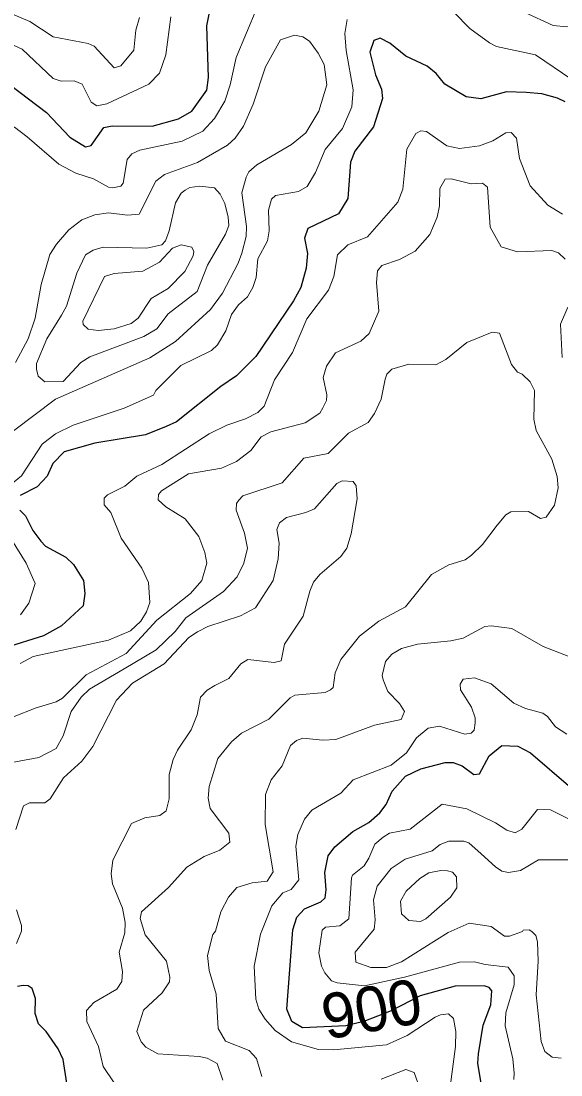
# Model space of a CAD drawing. Extents: x 294.2 to 320.3, y 7482.7 to 7510.7.
# Drawn here: x 318.172 to 319.135, y 7495.18 to 7497.059 of the extents above; entities that cross this region are included whole.
import ezdxf
from ezdxf.enums import TextEntityAlignment as Align

# ---------------------------------------------------------------- set-up
doc = ezdxf.new("R2010")
doc.units = 0
doc.header["$LTSCALE"] = 0.032
doc.layers.add('1', color=7, linetype='Continuous', lineweight=25)
doc.layers.add('2', color=7, linetype='Continuous', lineweight=13)
doc.layers.add('61', color=7, linetype='Continuous')

msp = doc.modelspace()

# ---------------------------------------------------------------- linework, layer by layer
at = {"layer": '1'}
for points in [[(318.1531, 7496.9451), (318.2173, 7496.896), (318.259, 7496.8522), (318.2869, 7496.8348), (318.2967, 7496.8371), (318.3194, 7496.8696), (318.3345, 7496.8726), (318.4059, 7496.8718), (318.4528, 7496.8847), (318.4766, 7496.8983), (318.5031, 7496.9361), (318.5061, 7496.9587), (318.5035, 7497.0509), (318.5126, 7497.0992)], [(319.1429, 7496.9152), (319.1293, 7496.922), (319.1013, 7496.9295), (319.0734, 7496.9318), (319.0382, 7496.9333), (318.9922, 7496.9205), (318.9665, 7496.9243), (318.9279, 7496.9469), (318.9124, 7496.9658), (318.8965, 7496.9786), (318.8588, 7496.9967), (318.83, 7497.0201), (318.8127, 7497.0285), (318.8013, 7497.0247), (318.7945, 7497.0035), (318.8043, 7496.9635), (318.8152, 7496.9378), (318.8167, 7496.9212), (318.8008, 7496.8706)], [(318.8008, 7496.8706), (318.7676, 7496.8275), (318.7596, 7496.8079), (318.7551, 7496.743), (318.7384, 7496.7158), (318.6833, 7496.6894), (318.6779, 7496.672)], [(318.6779, 7496.672), (318.6831, 7496.6448), (318.6809, 7496.6184), (318.671, 7496.5844), (318.6581, 7496.5602), (318.5908, 7496.4612), (318.5564, 7496.4265), (318.5285, 7496.4076), (318.4491, 7496.3449), (318.4309, 7496.3366), (318.3939, 7496.3215), (318.3031, 7496.3064), (318.2487, 7496.2913), (318.2283, 7496.2702), (318.2185, 7496.2475), (318.2004, 7496.2286), (318.1702, 7496.2135)], [(318.1693, 7496.1871), (318.1799, 7496.1773), (318.1927, 7496.1509), (318.2069, 7496.1318), (318.2152, 7496.1227), (318.2514, 7496.1031), (318.2656, 7496.0903), (318.2831, 7496.062), (318.2854, 7496.0386), (318.2823, 7496.0167), (318.2437, 7495.9812), (318.212, 7495.963), (318.1436, 7495.9419)], [(318.8843, 7495.3211), (318.8321, 7495.2947), (318.7834, 7495.2754), (318.7517, 7495.2679), (318.6739, 7495.2641), (318.655, 7495.2754), (318.6459, 7495.2973), (318.657, 7495.4387), (318.6638, 7495.4614), (318.6774, 7495.4765), (318.7067, 7495.4887), (318.7144, 7495.4957), (318.7163, 7495.5104), (318.7137, 7495.5411), (318.7201, 7495.5711), (318.7316, 7495.587), (318.7642, 7495.6144), (318.7923, 7495.6304), (318.812, 7495.6476), (318.8235, 7495.6624), (318.8344, 7495.6859), (318.858, 7495.7128), (318.8855, 7495.7262), (318.9289, 7495.737), (318.943, 7495.737), (318.9589, 7495.7313), (318.9799, 7495.716), (318.9902, 7495.7173), (319.0074, 7495.7492), (319.0298, 7495.7677), (319.0585, 7495.7664), (319.0808, 7495.7543), (319.1529, 7495.6925)], [(318.2533, 7495.1656), (318.2466, 7495.2075), (318.2378, 7495.2269), (318.2167, 7495.2576), (318.2029, 7495.271), (318.1968, 7495.2898), (318.1976, 7495.3165), (318.1918, 7495.3345), (318.1841, 7495.3389), (318.1752, 7495.3394), (318.1652, 7495.3378)], [(318.9966, 7495.2691), (319.01, 7495.3054), (319.0119, 7495.3303), (319.0074, 7495.3361), (318.9985, 7495.3393), (318.9468, 7495.3386), (318.8843, 7495.3211)], [(318.994, 7495.158), (318.987, 7495.2014), (318.9882, 7495.218), (318.9966, 7495.2691)]]:
    msp.add_lwpolyline(points, dxfattribs=at)
at = {"layer": '2'}
for points in [[(319.2034, 7496.931), (319.1945, 7496.9444), (319.1549, 7496.9553), (319.0898, 7496.9993), (319.0202, 7497.014), (319.0081, 7497.0204), (318.9729, 7497.0459), (318.9161, 7497.104)], [(319.1849, 7497.0893), (319.1632, 7497.0536), (319.146, 7497.0491), (319.1217, 7497.0516), (319.07, 7497.0753)], [(317.9833, 7496.8333), (317.9941, 7496.8537), (318.0133, 7496.8723), (318.0542, 7496.8831), (318.1295, 7496.8838), (318.1602, 7496.8703), (318.1825, 7496.8531), (318.2394, 7496.8039), (318.2693, 7496.788), (318.3011, 7496.7778), (318.328, 7496.7631), (318.3355, 7496.762), (318.3499, 7496.7647), (318.3539, 7496.7703), (318.3613, 7496.8121), (318.3694, 7496.8227), (318.3837, 7496.8288), (318.459, 7496.8448), (318.496, 7496.8627), (318.5171, 7496.8857), (318.5356, 7496.9163), (318.5452, 7496.9457), (318.5554, 7496.9942), (318.5924, 7497.0823)], [(318.1564, 7497.0715), (318.1876, 7497.0587), (318.2291, 7497.0312), (318.2917, 7497.0191), (318.3025, 7497.0146), (318.3377, 7496.9757), (318.3498, 7496.9795), (318.3728, 7497.0076), (318.3766, 7497.0427), (318.383, 7497.0657)], [(318.7539, 7497.0619), (318.7495, 7497.037), (318.752, 7497.007), (318.7648, 7496.9367), (318.7623, 7496.9061), (318.7457, 7496.8678), (318.7144, 7496.8301), (318.6971, 7496.7892), (318.6824, 7496.7643), (318.6671, 7496.7554), (318.6256, 7496.7484), (318.6186, 7496.7414), (318.6135, 7496.7222), (318.6147, 7496.6852), (318.6116, 7496.6673), (318.5943, 7496.6354), (318.5911, 7496.6022), (318.5854, 7496.5843), (318.5758, 7496.5677), (318.5598, 7496.553), (318.5471, 7496.5358), (318.5375, 7496.507), (318.5222, 7496.4822), (318.5119, 7496.4719), (318.4571, 7496.4451), (318.4124, 7496.4004), (318.4079, 7496.3921), (318.3556, 7496.3691), (318.2649, 7496.3385), (318.233, 7496.3232), (318.2092, 7496.3046), (318.1725, 7496.2481), (318.1397, 7496.2214)], [(318.307, 7496.908), (318.3249, 7496.9119), (318.3996, 7496.947), (318.4188, 7496.9661), (318.4303, 7496.9993), (318.4392, 7497.067)], [(318.1615, 7496.4502), (318.1844, 7496.4924), (318.1966, 7496.5294), (318.2074, 7496.5894), (318.2233, 7496.643), (318.2349, 7496.6615), (318.2572, 7496.6871), (318.2802, 7496.705), (318.3032, 7496.7139), (318.3275, 7496.7171), (318.3619, 7496.7132), (318.3824, 7496.7152), (318.4125, 7496.7737), (318.4275, 7496.7856), (318.4869, 7496.8072), (318.5402, 7496.8378), (318.5541, 7496.8507), (318.5685, 7496.8717), (318.586, 7496.9112), (318.6083, 7496.9776), (318.6346, 7497.0255), (318.6595, 7497.0338), (318.6748, 7497.0312), (318.6863, 7497.0236), (318.7022, 7497.0019), (318.7125, 7496.9815), (318.7176, 7496.9457), (318.7035, 7496.8985), (318.6799, 7496.8601), (318.6543, 7496.8391), (318.5924, 7496.8026), (318.5783, 7496.7905), (318.5733, 7496.781), (318.5656, 7496.7529), (318.5739, 7496.6929)], [(318.1461, 7497.0217), (318.1736, 7497.0089)], [(318.1736, 7497.0089), (318.2291, 7496.9571), (318.2432, 7496.952), (318.2668, 7496.9527), (318.2808, 7496.947), (318.2968, 7496.9144), (318.307, 7496.908)], [(318.8957, 7496.8621), (318.8855, 7496.8633), (318.8765, 7496.8588), (318.8606, 7496.8308), (318.8529, 7496.7593), (318.844, 7496.7363), (318.7903, 7496.6743)], [(319.1383, 7496.7152), (319.1121, 7496.7311), (319.0802, 7496.7656), (319.0617, 7496.8142), (319.056, 7496.8506), (319.0464, 7496.8608), (319.0368, 7496.8601), (319.0138, 7496.8455), (318.9902, 7496.8365), (318.9544, 7496.832), (318.9315, 7496.8365), (318.8957, 7496.8621)], [(319.1428, 7496.6347), (319.1313, 7496.6462), (319.1192, 7496.6501), (319.0579, 7496.6475), (319.0285, 7496.6565), (319.0093, 7496.6916), (319.0042, 7496.7631), (318.9953, 7496.7701), (318.9749, 7496.7688), (318.9397, 7496.7778), (318.9289, 7496.7771), (318.9193, 7496.7605), (318.9186, 7496.7299), (318.9142, 7496.7095), (318.9014, 7496.6788), (318.8753, 7496.6488), (318.8472, 7496.6341), (318.8159, 7496.6232), (318.8082, 7496.6137), (318.8063, 7496.5933), (318.8101, 7496.5422), (318.7929, 7496.5019), (318.7782, 7496.4885), (318.7329, 7496.4675), (318.7169, 7496.4439), (318.7112, 7496.4234), (318.7176, 7496.3928), (318.7169, 7496.3826), (318.7105, 7496.3697), (318.7048, 7496.3602), (318.6786, 7496.3429), (318.6173, 7496.327), (318.6001, 7496.3181), (318.5816, 7496.2938), (318.556, 7496.274), (318.5292, 7496.2619), (318.4705, 7496.2517), (318.4226, 7496.2217), (318.4168, 7496.2153), (318.4162, 7496.2057), (318.4303, 7496.1932)], [(318.5739, 7496.6929), (318.5733, 7496.675), (318.5656, 7496.6456), (318.5592, 7496.6277), (318.5311, 7496.5741), (318.5101, 7496.5449), (318.4475, 7496.4879)], [(318.7903, 7496.6743), (318.7552, 7496.6603), (318.7367, 7496.6424), (318.7303, 7496.6035), (318.7207, 7496.5792), (318.6818, 7496.5281), (318.6563, 7496.4681), (318.6243, 7496.4196), (318.6058, 7496.3723), (318.5943, 7496.3615), (318.5726, 7496.35), (318.5388, 7496.3385), (318.5075, 7496.3232), (318.4232, 7496.2683), (318.3785, 7496.2478), (318.3568, 7496.23), (318.3262, 7496.2146), (318.3199, 7496.2085), (318.3198, 7496.1968), (318.3319, 7496.1827), (318.3504, 7496.1374), (318.3875, 7496.0838), (318.3989, 7496.0582), (318.4015, 7496.0225), (318.3958, 7496.0059), (318.3856, 7495.9892), (318.367, 7495.972), (318.3275, 7495.9554), (318.1934, 7495.926), (318.1704, 7495.9139)], [(319.1377, 7496.4592), (319.1345, 7496.5185), (319.1479, 7496.5492)], [(318.3932, 7495.43), (318.3843, 7495.4593), (318.3868, 7495.4708), (318.4347, 7495.5142), (318.4679, 7495.5506), (318.4986, 7495.5698), (318.5267, 7495.5812), (318.5445, 7495.5953), (318.5426, 7495.6113), (318.5094, 7495.6553), (318.5056, 7495.6739), (318.5075, 7495.6943), (318.5228, 7495.7441), (318.5471, 7495.7741), (318.565, 7495.7894), (318.6141, 7495.8143), (318.6518, 7495.8526), (318.6601, 7495.8571), (318.7144, 7495.8622), (318.7239, 7495.8667), (318.729, 7495.8711), (318.7322, 7495.8973), (318.7424, 7495.9209), (318.7757, 7495.9624), (318.8102, 7495.9892), (318.858, 7496.0148), (318.9046, 7496.0722), (318.9353, 7496.0895), (318.9647, 7496.0984), (318.9755, 7496.1067), (318.9953, 7496.1259), (319.0215, 7496.1604), (319.0368, 7496.1789), (319.0457, 7496.184), (319.0776, 7496.1846), (319.0987, 7496.1725), (319.1089, 7496.1744), (319.1236, 7496.1961), (319.1306, 7496.2268), (319.1287, 7496.2472), (319.1191, 7496.2779), (319.091, 7496.3289), (319.0872, 7496.3494), (319.0879, 7496.4004), (319.0802, 7496.4157), (319.0662, 7496.4298), (319.0578, 7496.433), (319.047, 7496.447), (319.0259, 7496.5026), (319.0125, 7496.5045), (318.9672, 7496.486), (318.9302, 7496.456), (318.9123, 7496.4464), (318.8638, 7496.4476), (318.8337, 7496.4387), (318.8248, 7496.4298), (318.8216, 7496.4209), (318.8146, 7496.3851), (318.8025, 7496.3596), (318.791, 7496.3436), (318.7559, 7496.3244), (318.7201, 7496.288), (318.6767, 7496.2798), (318.6378, 7496.2357), (318.5675, 7496.2127), (318.5605, 7496.2051), (318.556, 7496.1993), (318.5554, 7496.1872), (318.5707, 7496.1463), (318.5758, 7496.1195), (318.5694, 7496.0927), (318.5573, 7496.0684), (318.5331, 7496.0422), (318.466, 7495.995), (318.4468, 7495.9707), (318.413, 7495.9382), (318.3555, 7495.9043), (318.2936, 7495.8679), (318.2789, 7495.8539), (318.261, 7495.8284), (318.247, 7495.7849), (318.2342, 7495.7619), (318.2036, 7495.746), (318.1231, 7495.7313)], [(318.4475, 7496.4879), (318.4015, 7496.4585), (318.233, 7496.3851), (318.1582, 7496.3283)], [(318.3358, 7495.5628), (318.3689, 7495.6285), (318.3926, 7495.6387), (318.4194, 7495.6426), (318.4309, 7495.6508), (318.436, 7495.6726), (318.436, 7495.716), (318.443, 7495.7428), (318.4507, 7495.7594), (318.4755, 7495.7952), (318.4858, 7495.822), (318.4921, 7495.8539), (318.5037, 7495.866), (318.5177, 7495.8743), (318.5426, 7495.8871), (318.5643, 7495.9133), (318.5765, 7495.9209), (318.6237, 7495.9158), (318.6358, 7495.9184), (318.6422, 7495.9484), (318.6754, 7495.9982), (318.6869, 7496.0429), (318.6939, 7496.0588), (318.7048, 7496.0722), (318.7424, 7496.1048), (318.7533, 7496.1195), (318.761, 7496.145), (318.7718, 7496.2076), (318.7699, 7496.2306), (318.7648, 7496.2382), (318.745, 7496.2395), (318.7354, 7496.2344), (318.6952, 7496.1897), (318.6799, 7496.1827), (318.6454, 7496.1738), (318.6333, 7496.1648), (318.6282, 7496.1527), (318.6326, 7496.1284), (318.6307, 7496.1004), (318.6218, 7496.062), (318.5899, 7496.0129), (318.5637, 7495.9988), (318.505, 7495.9797), (318.4864, 7495.9701), (318.4711, 7495.9599), (318.427, 7495.9133), (318.3705, 7495.8789), (318.3423, 7495.8483), (318.3, 7495.7658), (318.2802, 7495.7396), (318.2476, 7495.7096), (318.2234, 7495.6725), (318.2144, 7495.6655), (318.187, 7495.6655), (318.1761, 7495.6598), (318.1621, 7495.6177)], [(318.4303, 7496.1932), (318.4647, 7496.1718), (318.489, 7496.1399), (318.4998, 7496.1118), (318.5036, 7496.0927), (318.4941, 7496.062), (318.4743, 7496.0384)], [(318.1547, 7496.1348), (318.1806, 7496.0927), (318.1966, 7496.0563), (318.1857, 7496.0212), (318.171, 7496.0007)], [(318.4743, 7496.0384), (318.4143, 7495.9912), (318.3594, 7495.9318), (318.2878, 7495.8935), (318.2457, 7495.852), (318.2342, 7495.8456), (318.1985, 7495.8347), (318.1563, 7495.8181)], [(318.618, 7495.7064), (318.6377, 7495.7313), (318.6524, 7495.7677), (318.6633, 7495.7766), (318.6748, 7495.7805), (318.7106, 7495.7772), (318.7335, 7495.7785), (318.8025, 7495.8035), (318.8503, 7495.8137), (318.8561, 7495.8283), (318.8471, 7495.8424), (318.8261, 7495.8641), (318.8178, 7495.8846), (318.8165, 7495.8922), (318.8223, 7495.9171), (318.8338, 7495.9305), (318.851, 7495.9407), (318.8791, 7495.9484), (318.9391, 7495.9541), (318.9608, 7495.9592), (318.9997, 7495.9797), (319.0106, 7495.981), (319.0477, 7495.9764), (319.1039, 7495.9439), (319.1511, 7495.9254)], [(318.5879, 7495.3738), (318.5994, 7495.4312), (318.6192, 7495.4817), (318.639, 7495.5047), (318.6537, 7495.511), (318.6678, 7495.5283), (318.662, 7495.5883), (318.6658, 7495.6087), (318.6779, 7495.6362), (318.6907, 7495.6521), (318.7425, 7495.6828), (318.7648, 7495.7064), (318.8325, 7495.7325), (318.8599, 7495.7543), (318.8778, 7495.7811), (318.8983, 7495.7983), (318.9187, 7495.8022), (318.964, 7495.7875), (318.9749, 7495.7894), (318.9806, 7495.7951), (318.9825, 7495.8079), (318.9825, 7495.8169), (318.9755, 7495.836), (318.9564, 7495.8667), (318.9557, 7495.8769), (318.9608, 7495.8858), (318.9813, 7495.8883), (319.0106, 7495.8775), (319.0515, 7495.843), (319.0719, 7495.8334), (319.1032, 7495.8252), (319.1115, 7495.8194), (319.1255, 7495.8009), (319.146, 7495.7875)], [(318.5566, 7495.5142), (318.5841, 7495.5225), (318.6109, 7495.5257), (318.6218, 7495.5423), (318.6077, 7495.6266), (318.6083, 7495.6802), (318.618, 7495.7064)], [(318.7565, 7495.4586), (318.7616, 7495.5315), (318.7635, 7495.5366), (318.784, 7495.5531), (318.7922, 7495.5666), (318.8031, 7495.5915), (318.8178, 7495.6043), (318.8293, 7495.6112), (318.8663, 7495.6183), (318.9231, 7495.663), (318.9672, 7495.6547), (319.0183, 7495.6298), (319.0387, 7495.6164), (319.0534, 7495.6119), (319.0655, 7495.6183), (319.0936, 7495.6534), (319.1166, 7495.6528), (319.1511, 7495.6355)], [(319.1358, 7495.2103), (319.1198, 7495.2116), (319.1064, 7495.2218), (319.1, 7495.2397), (319.091, 7495.3227), (319.0949, 7495.3827), (319.0936, 7495.4172), (319.0904, 7495.4287), (319.0834, 7495.4357), (319.0789, 7495.4388), (319.0681, 7495.4382), (319.0668, 7495.4357), (319.0438, 7495.4274), (319.0349, 7495.4274), (319.0106, 7495.4446), (318.9716, 7495.451), (318.934, 7495.4344), (318.851, 7495.3821), (318.8242, 7495.3718), (318.7961, 7495.3718), (318.7692, 7495.3814), (318.768, 7495.3993), (318.8018, 7495.4402), (318.8037, 7495.4568), (318.8006, 7495.4925), (318.8076, 7495.5168), (318.8325, 7495.548), (318.8574, 7495.5647), (318.9053, 7495.58), (318.9199, 7495.5908), (318.9353, 7495.5972), (318.9621, 7495.5972), (318.971, 7495.594), (318.9927, 7495.5742), (319.0183, 7495.5512), (319.0297, 7495.5436), (319.0419, 7495.541), (319.063, 7495.5448), (319.0955, 7495.5634), (319.1651, 7495.5634)], [(318.3466, 7495.3993), (318.3568, 7495.4338), (318.3575, 7495.4517), (318.353, 7495.4772), (318.3351, 7495.5206), (318.3325, 7495.5385), (318.3358, 7495.5628)], [(318.6014, 7495.1771), (318.5918, 7495.2097), (318.579, 7495.2237), (318.5368, 7495.2403), (318.5235, 7495.2627), (318.5202, 7495.324), (318.5075, 7495.3661), (318.5043, 7495.3929), (318.5139, 7495.4306), (318.519, 7495.4363), (318.5286, 7495.4708), (318.5419, 7495.497), (318.5566, 7495.5142)], [(318.1634, 7495.4746), (318.1723, 7495.4466), (318.1723, 7495.4363), (318.1634, 7495.4146)], [(318.7137, 7495.3623), (318.708, 7495.3738), (318.7035, 7495.398), (318.7093, 7495.4382), (318.715, 7495.4434), (318.7405, 7495.4459), (318.7565, 7495.4586)], [(318.3785, 7495.2576), (318.39, 7495.2959), (318.4238, 7495.3265), (318.4366, 7495.3463), (318.4372, 7495.3546), (318.4315, 7495.3827), (318.3932, 7495.43)], [(318.3377, 7495.1662), (318.3185, 7495.195), (318.3102, 7495.2308), (318.2891, 7495.2754), (318.2885, 7495.2952), (318.3019, 7495.3093), (318.3427, 7495.3329), (318.3517, 7495.347), (318.353, 7495.3648), (318.3466, 7495.3993)], [(319.0515, 7495.172), (319.0521, 7495.1835), (319.0496, 7495.209), (319.0361, 7495.2678), (319.0368, 7495.2908), (319.0521, 7495.3406), (319.0521, 7495.3571), (319.0413, 7495.3724), (319.0004, 7495.3769), (318.9812, 7495.3821), (318.9544, 7495.3814), (318.8561, 7495.3546), (318.7846, 7495.3392), (318.7361, 7495.3444), (318.7259, 7495.3482), (318.7137, 7495.3623)], [(318.7029, 7495.2256), (318.6544, 7495.239), (318.625, 7495.2595), (318.6077, 7495.2793), (318.5963, 7495.2972), (318.5905, 7495.315), (318.5879, 7495.3738)], [(318.9378, 7495.1592), (318.9474, 7495.2308), (318.948, 7495.2576), (318.9438, 7495.2808), (318.9346, 7495.2888), (318.9206, 7495.2876), (318.911, 7495.2831), (318.8612, 7495.2505), (318.8242, 7495.2339), (318.7297, 7495.225), (318.7029, 7495.2256)], [(318.5317, 7495.1707), (318.5215, 7495.2007), (318.5037, 7495.2103), (318.4896, 7495.2128), (318.4156, 7495.2179), (318.3945, 7495.2295), (318.3862, 7495.239), (318.3785, 7495.2576)], [(318.8829, 7495.158), (318.8733, 7495.1847), (318.8587, 7495.1899), (318.8142, 7495.1725)]]:
    msp.add_lwpolyline(points, dxfattribs=at)
for points in [[(318.2437, 7496.5351), (318.2176, 7496.4924), (318.1991, 7496.4489), (318.1991, 7496.4387), (318.2023, 7496.426), (318.2144, 7496.4157), (318.247, 7496.4164), (318.2783, 7496.4502), (318.2942, 7496.4604), (318.3907, 7496.4968), (318.4143, 7496.5102), (318.4341, 7496.5371), (318.4858, 7496.5773), (318.5043, 7496.6239), (318.5369, 7496.6794), (318.5426, 7496.6948), (318.5413, 7496.7095), (318.5356, 7496.7337), (318.5273, 7496.7503), (318.5171, 7496.7618), (318.4909, 7496.765), (318.473, 7496.7624), (318.4647, 7496.758), (318.4577, 7496.7522), (318.4475, 7496.735), (318.436, 7496.6852), (318.4296, 7496.6673), (318.4232, 7496.6603), (318.3964, 7496.6545), (318.3185, 7496.6558), (318.3006, 7496.6507), (318.2866, 7496.6424), (318.2712, 7496.6099), (318.2528, 7496.5511)], [(318.3683, 7496.5198), (318.3377, 7496.5102), (318.3096, 7496.5077), (318.2917, 7496.5096), (318.2827, 7496.5179), (318.2821, 7496.5243), (318.3204, 7496.6035), (318.3377, 7496.6092), (318.3888, 7496.613), (318.4188, 7496.6296), (318.4423, 7496.6545), (318.4577, 7496.6603), (318.4768, 7496.6558), (318.4801, 7496.6482), (318.4788, 7496.6405), (318.4641, 7496.6124), (318.4341, 7496.5824), (318.4041, 7496.5645), (318.3805, 7496.5294)], [(318.8835, 7495.5301), (318.8593, 7495.5078), (318.8491, 7495.4899), (318.851, 7495.4676), (318.8638, 7495.4554), (318.8848, 7495.4536), (318.8944, 7495.4587), (318.9384, 7495.497), (318.9493, 7495.5136), (318.9487, 7495.5334), (318.9417, 7495.5417), (318.9327, 7495.5442), (318.9212, 7495.5449), (318.8995, 7495.5404)]]:
    msp.add_lwpolyline(points, close=True, dxfattribs=at)

# ---------------------------------------------------------------- texts
at = {"layer": '61'}
msp.add_text('900', height=0.08, rotation=10.128, dxfattribs=at).set_placement((318.8043, 7495.2586), align=Align.CENTER)

doc.saveas('drawing.dxf')
